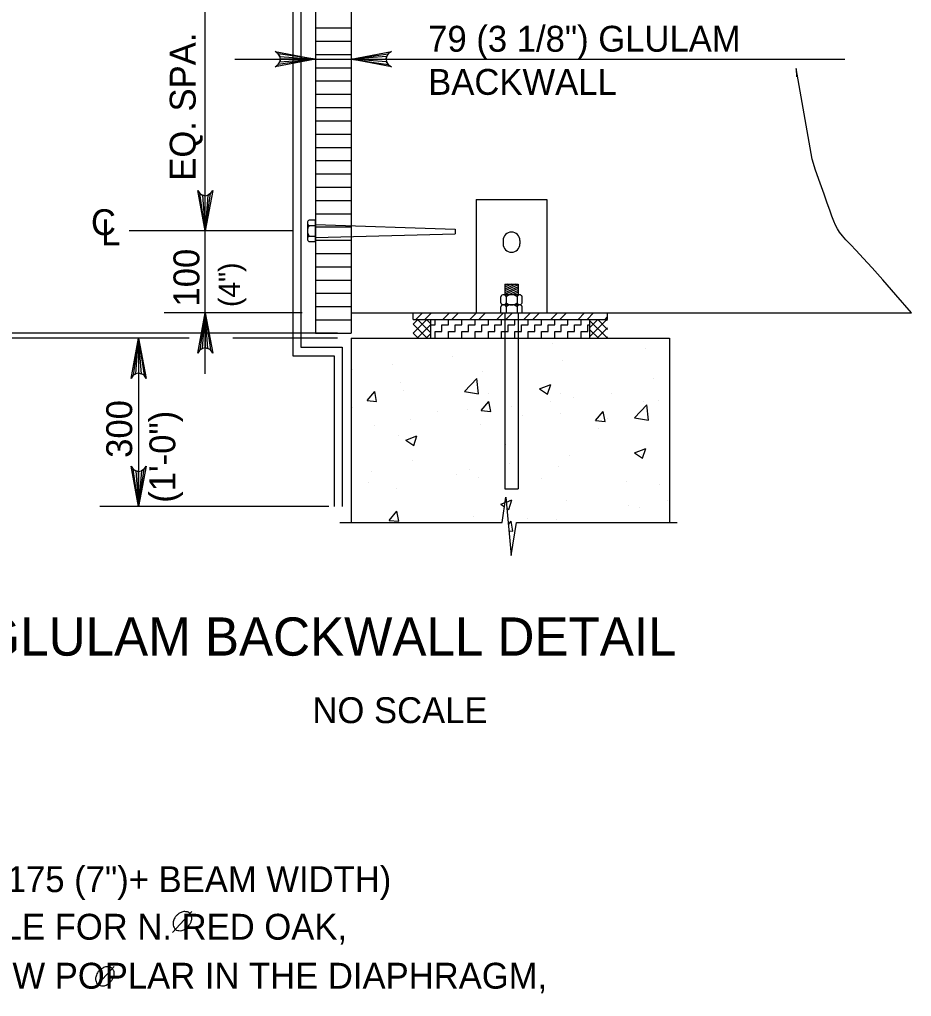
# Model space of a CAD drawing. Extents: x -13 to 81, y -176 to 0.
# Drawn here: x 47.852 to 51.986, y -10.168 to -5.639 of the extents above; entities that cross this region are included whole.
import ezdxf

# ---------------------------------------------------------------- set-up
doc = ezdxf.new("R2010")
doc.units = 0
for name, color, linetype in [('Level 3', 7, 'Continuous'), ('Level 4', 7, 'Continuous'), ('Level 5', 7, 'Continuous'), ('Level 7', 7, 'Continuous'), ('Level 8', 7, 'Continuous')]:
    doc.layers.add(name, color=color, linetype=linetype)

msp = doc.modelspace()

# ---------------------------------------------------------------- linework, layer by layer
at = {"layer": 'Level 3'}
for p, q in [((48.7129, -6.6186), (48.7129, -5.3997)), ((48.8506, -5.8229), (51.677, -5.8229)), ((49.1216, -6.6186), (48.3609, -6.6186)), ((48.7129, -7.2812), (48.7129, -6.6186)), ((49.1623, -6.9992), (48.5222, -6.9992)), ((48.6545, -7.0929), (47.2888, -7.0929)), ((49.1622, -7.0929), (48.8196, -7.0929)), ((48.3767, -7.1164), (48.2243, -7.1164)), ((48.4043, -7.1164), (48.4043, -7.8965)), ((49.2853, -7.8965), (48.2243, -7.8965))]:
    msp.add_line(p, q, dxfattribs=at)
for points in [[(49.2237, -5.8229), (49.0373, -5.8578), (49.0517, -5.8479), (49.0591, -5.8354), (49.0613, -5.8229), (49.0591, -5.8104), (49.0517, -5.7979), (49.0373, -5.7879), (49.2237, -5.8229), (49.0517, -5.7979), (49.0591, -5.8104), (49.2237, -5.8229), (49.0613, -5.8229), (49.0591, -5.8354), (49.2237, -5.8229), (49.0517, -5.8479)], [(49.3892, -5.8229), (49.5756, -5.7879), (49.5613, -5.7979), (49.5538, -5.8104), (49.5517, -5.8229), (49.5538, -5.8354), (49.5613, -5.8479), (49.5756, -5.8578), (49.3892, -5.8229), (49.5613, -5.8479), (49.5538, -5.8354), (49.3892, -5.8229), (49.5517, -5.8229), (49.5538, -5.8104), (49.3892, -5.8229), (49.5613, -5.7979)], [(48.7129, -6.6186), (48.678, -6.4322), (48.6879, -6.4465), (48.7004, -6.4539), (48.7129, -6.4561), (48.7254, -6.4539), (48.7379, -6.4465), (48.7478, -6.4322), (48.7129, -6.6186), (48.7379, -6.4465), (48.7254, -6.4539), (48.7129, -6.6186), (48.7129, -6.4561), (48.7004, -6.4539), (48.7129, -6.6186), (48.6879, -6.4465)], [(48.7129, -6.9992), (48.7478, -7.1856), (48.7379, -7.1712), (48.7254, -7.1638), (48.7129, -7.1617), (48.7004, -7.1638), (48.6879, -7.1712), (48.678, -7.1856), (48.7129, -6.9992), (48.6879, -7.1712), (48.7004, -7.1638), (48.7129, -6.9992), (48.7129, -7.1617), (48.7254, -7.1638), (48.7129, -6.9992), (48.7379, -7.1712)], [(48.4043, -7.1164), (48.4393, -7.3028), (48.4293, -7.2885), (48.4168, -7.2811), (48.4043, -7.2789), (48.3918, -7.2811), (48.3793, -7.2885), (48.3694, -7.3028), (48.4043, -7.1164), (48.3793, -7.2885), (48.3918, -7.2811), (48.4043, -7.1164), (48.4043, -7.2789), (48.4168, -7.2811), (48.4043, -7.1164), (48.4293, -7.2885)], [(48.4043, -7.8965), (48.3694, -7.7101), (48.3793, -7.7244), (48.3918, -7.7318), (48.4043, -7.734), (48.4168, -7.7318), (48.4293, -7.7244), (48.4393, -7.7101), (48.4043, -7.8965), (48.4293, -7.7244), (48.4168, -7.7318), (48.4043, -7.8965), (48.4043, -7.734), (48.3918, -7.7318), (48.4043, -7.8965), (48.3793, -7.7244)]]:
    msp.add_lwpolyline(points, dxfattribs=at)
at = {"layer": 'Level 4'}
for p, q in [((48.5608, -9.8718), (48.6504, -9.7737)), ((48.2018, -10.1275), (48.2914, -10.0294))]:
    msp.add_line(p, q, dxfattribs=at)
for points in [[(48.6412, -9.7833), (48.6341, -9.7779), (48.6271, -9.776), (48.6184, -9.7752), (48.6133, -9.7752), (48.6047, -9.7772), (48.5968, -9.7808), (48.5913, -9.7839), (48.5808, -9.7924), (48.5724, -9.8032), (48.5674, -9.8133), (48.5645, -9.8225), (48.5636, -9.8312), (48.5645, -9.8385), (48.5682, -9.8491), (48.572, -9.8545), (48.5796, -9.8604), (48.5912, -9.8632), (48.6044, -9.8628), (48.6212, -9.8551), (48.6333, -9.8447), (48.6425, -9.8319), (48.6485, -9.8187), (48.6505, -9.804), (48.6479, -9.7945), (48.6416, -9.7833)], [(48.2822, -10.0391), (48.2751, -10.0337), (48.2681, -10.0317), (48.2594, -10.031), (48.2542, -10.031), (48.2458, -10.0329), (48.2377, -10.0366), (48.2323, -10.0397), (48.2218, -10.0482), (48.2134, -10.0589), (48.2084, -10.069), (48.2055, -10.0782), (48.2046, -10.0869), (48.2055, -10.0942), (48.2092, -10.1048), (48.213, -10.1102), (48.2206, -10.1162), (48.2322, -10.1189), (48.2454, -10.1185), (48.2622, -10.1108), (48.2743, -10.1004), (48.2835, -10.0877), (48.2895, -10.0744), (48.2915, -10.0597), (48.2889, -10.0503), (48.2826, -10.0391)]]:
    msp.add_spline(points, degree=3, dxfattribs=at)
at = {"layer": 'Level 5'}
for p, q in [((49.2237, -3.1736), (49.2237, -7.0929)), ((49.119, -3.2621), (49.119, -7.198)), ((49.156, -3.3007), (49.156, -7.1582)), ((49.3892, -3.8148), (49.3892, -7.0929)), ((49.9695, -6.4742), (50.2958, -6.4742)), ((49.9695, -6.4742), (49.9695, -6.9992)), ((50.2958, -6.4742), (50.2958, -6.9992)), ((49.1863, -6.5811), (49.1863, -6.657)), ((49.2237, -6.5888), (49.8712, -6.6107)), ((49.8712, -6.6107), (49.8712, -6.6327)), ((49.2237, -6.6502), (49.8712, -6.6327)), ((50.0936, -6.6633), (50.0936, -6.679)), ((50.1717, -6.6633), (50.1717, -6.679)), ((50.1019, -6.8662), (50.1019, -6.9155)), ((50.1019, -6.8662), (50.1634, -6.8662)), ((50.1326, -6.8662), (50.1019, -6.8803)), ((50.1512, -6.8662), (50.1019, -6.8888)), ((50.1139, -6.8662), (50.1019, -6.8717)), ((50.1634, -6.8692), (50.1019, -6.8974)), ((50.1634, -6.8777), (50.1019, -6.9059)), ((50.1634, -6.8662), (50.1634, -6.9155)), ((50.0827, -6.9529), (50.0827, -6.9243)), ((50.171, -6.9155), (50.0952, -6.9155)), ((50.1634, -6.8862), (50.1019, -6.9145)), ((50.1086, -6.9243), (50.1086, -6.9529)), ((50.1634, -6.8948), (50.1182, -6.9156)), ((50.1634, -6.9034), (50.137, -6.9155)), ((50.1634, -6.9119), (50.1557, -6.9155)), ((50.1585, -6.9243), (50.1585, -6.9529)), ((50.1827, -6.9529), (50.1827, -6.9243)), ((50.0827, -6.9992), (50.0827, -6.9706)), ((50.171, -6.9617), (50.0952, -6.9617)), ((50.1086, -6.9706), (50.1086, -6.9992)), ((50.1585, -6.9706), (50.1585, -6.9992)), ((50.1827, -6.9992), (50.1827, -6.9706)), ((49.3892, -6.9992), (51.9864, -6.9992)), ((49.6763, -6.9992), (50.5782, -6.9992)), ((49.6763, -7.03), (49.6763, -6.9992)), ((49.6892, -7.03), (49.7199, -6.9992)), ((49.7309, -7.03), (49.7617, -6.9992)), ((49.8144, -7.03), (49.8453, -6.9992)), ((49.8562, -7.03), (49.887, -6.9992)), ((49.9397, -7.03), (49.9705, -6.9992)), ((49.9814, -7.03), (50.0123, -6.9992)), ((50.065, -7.03), (50.0957, -6.9992)), ((50.0827, -6.9992), (50.1827, -6.9992)), ((50.1019, -6.9992), (50.1019, -7.8142)), ((50.1067, -7.03), (50.1375, -6.9992)), ((50.1634, -6.9992), (50.1634, -7.8142)), ((50.1902, -7.03), (50.2211, -6.9992)), ((50.232, -7.03), (50.2628, -6.9992)), ((50.3155, -7.03), (50.3463, -6.9992)), ((50.3573, -7.03), (50.3881, -6.9992)), ((50.4408, -7.03), (50.4716, -6.9992)), ((50.4826, -7.03), (50.5133, -6.9992)), ((50.5661, -7.03), (50.5782, -7.0177)), ((50.5782, -7.03), (50.5782, -6.9992)), ((49.6763, -7.03), (50.5782, -7.03)), ((49.6763, -7.0934), (49.7398, -7.03)), ((49.6763, -7.0517), (49.698, -7.03)), ((49.7417, -7.1164), (49.6763, -7.0511)), ((49.6951, -7.1164), (49.7582, -7.0532)), ((49.7582, -7.0912), (49.697, -7.03)), ((49.7582, -7.0495), (49.7387, -7.03)), ((49.7582, -7.1164), (49.7582, -7.03)), ((49.7582, -7.0552), (49.7792, -7.0552)), ((49.7792, -7.0552), (49.7792, -7.03)), ((49.8099, -7.0552), (49.8407, -7.0552)), ((49.8099, -7.0859), (49.8099, -7.0552)), ((49.8407, -7.0552), (49.8407, -7.03)), ((49.8714, -7.0552), (49.9022, -7.0552)), ((49.8714, -7.0859), (49.8714, -7.0552)), ((49.9022, -7.0552), (49.9022, -7.03)), ((49.9329, -7.0552), (49.9637, -7.0552)), ((49.9329, -7.0859), (49.9329, -7.0552)), ((49.9637, -7.0552), (49.9637, -7.03)), ((49.9944, -7.0552), (50.0252, -7.0552)), ((49.9944, -7.0859), (49.9944, -7.0552)), ((50.0252, -7.0552), (50.0252, -7.03)), ((50.0559, -7.0552), (50.0867, -7.0552)), ((50.0559, -7.0859), (50.0559, -7.0552)), ((50.0867, -7.0552), (50.0867, -7.03)), ((50.1175, -7.0552), (50.1482, -7.0552)), ((50.1175, -7.0859), (50.1175, -7.0552)), ((50.1482, -7.0552), (50.1482, -7.03)), ((50.179, -7.0552), (50.2097, -7.0552)), ((50.179, -7.0859), (50.179, -7.0552)), ((50.2097, -7.0552), (50.2097, -7.03)), ((50.2405, -7.0552), (50.2712, -7.0552)), ((50.2405, -7.0859), (50.2405, -7.0552)), ((50.2712, -7.0552), (50.2712, -7.03)), ((50.302, -7.0552), (50.3327, -7.0552)), ((50.302, -7.0859), (50.302, -7.0552)), ((50.3327, -7.0552), (50.3327, -7.03)), ((50.3635, -7.0552), (50.3942, -7.0552)), ((50.3635, -7.0859), (50.3635, -7.0552)), ((50.3942, -7.0552), (50.3942, -7.03)), ((50.425, -7.0552), (50.4558, -7.0552)), ((50.425, -7.0859), (50.425, -7.0552)), ((50.4558, -7.0552), (50.4558, -7.03)), ((50.4866, -7.0552), (50.4963, -7.0552)), ((50.4866, -7.0859), (50.4866, -7.0552)), ((50.4964, -7.0667), (50.5332, -7.03)), ((50.4964, -7.1085), (50.5749, -7.03)), ((50.4964, -7.1164), (50.4964, -7.03)), ((50.5768, -7.1164), (50.4964, -7.036)), ((50.5782, -7.0761), (50.5322, -7.03)), ((50.5782, -7.0343), (50.5739, -7.03)), ((49.6999, -7.1164), (49.6763, -7.0928)), ((49.7368, -7.1164), (49.7582, -7.0951)), ((49.7792, -7.0859), (49.8099, -7.0859)), ((49.7792, -7.1164), (49.7792, -7.0859)), ((49.8407, -7.0859), (49.8714, -7.0859)), ((49.8407, -7.1164), (49.8407, -7.0859)), ((49.9022, -7.0859), (49.9329, -7.0859)), ((49.9022, -7.1164), (49.9022, -7.0859)), ((49.9637, -7.0859), (49.9944, -7.0859)), ((49.9637, -7.1164), (49.9637, -7.0859)), ((50.0252, -7.0859), (50.0559, -7.0859)), ((50.0252, -7.1164), (50.0252, -7.0859)), ((50.0867, -7.0859), (50.1175, -7.0859)), ((50.0867, -7.1164), (50.0867, -7.0859)), ((50.1482, -7.0859), (50.179, -7.0859)), ((50.1482, -7.1164), (50.1482, -7.0859)), ((50.2097, -7.0859), (50.2405, -7.0859)), ((50.2097, -7.1164), (50.2097, -7.0859)), ((50.2712, -7.0859), (50.302, -7.0859)), ((50.2712, -7.1164), (50.2712, -7.0859)), ((50.3327, -7.0859), (50.3635, -7.0859)), ((50.3327, -7.1164), (50.3327, -7.0859)), ((50.3942, -7.0859), (50.425, -7.0859)), ((50.3942, -7.1164), (50.3942, -7.0859)), ((50.4558, -7.0859), (50.4866, -7.0859)), ((50.4558, -7.1164), (50.4558, -7.0859)), ((50.5351, -7.1164), (50.4964, -7.0777)), ((50.5302, -7.1164), (50.5782, -7.0684)), ((50.572, -7.1164), (50.5782, -7.1102)), ((49.3892, -7.1164), (50.8656, -7.1164)), ((49.3892, -7.1164), (49.3892, -7.9703)), ((50.3249, -7.1409), (50.3249, -7.1409)), ((50.5097, -7.1166), (50.5097, -7.1166)), ((50.8656, -7.1164), (50.8656, -7.9703)), ((49.119, -7.198), (49.3108, -7.198)), ((49.156, -7.1582), (49.3478, -7.1582)), ((49.3108, -7.198), (49.3108, -7.8965)), ((49.3478, -7.1582), (49.3478, -7.8965)), ((50.7522, -7.1664), (50.7522, -7.1664)), ((49.5791, -7.2391), (49.5791, -7.2391)), ((49.8587, -7.2022), (49.8587, -7.2022)), ((50.3688, -7.2218), (50.3688, -7.2218)), ((49.3943, -7.2634), (49.3943, -7.2634)), ((49.9959, -7.269), (49.9959, -7.269)), ((49.6169, -7.321), (49.6169, -7.321)), ((49.9145, -7.3636), (49.972, -7.3037)), ((49.9802, -7.3738), (49.972, -7.3037)), ((50.2627, -7.351), (50.3145, -7.3312)), ((50.2995, -7.3758), (50.3145, -7.3312)), ((50.7902, -7.3012), (50.7902, -7.3012)), ((49.4632, -7.4059), (49.4988, -7.3636)), ((49.5073, -7.4098), (49.4988, -7.3636)), ((49.6317, -7.3572), (49.6317, -7.3572)), ((49.9145, -7.3636), (49.9802, -7.3738)), ((50.0257, -7.3739), (50.0257, -7.3739)), ((50.2627, -7.351), (50.2995, -7.3758)), ((50.3597, -7.3751), (50.3597, -7.3751)), ((50.5951, -7.3709), (50.5951, -7.3709)), ((49.4632, -7.4059), (49.5073, -7.4098)), ((49.9927, -7.4522), (50.0282, -7.4098)), ((50.0368, -7.4562), (50.0282, -7.4099)), ((50.3155, -7.4078), (50.3155, -7.4078)), ((50.4198, -7.3905), (50.4198, -7.3905)), ((50.7023, -7.4858), (50.7598, -7.4259)), ((50.7432, -7.4122), (50.7432, -7.4122)), ((50.7679, -7.496), (50.7598, -7.4259)), ((50.8138, -7.4072), (50.8138, -7.4072)), ((49.3933, -7.4398), (49.3933, -7.4398)), ((49.7873, -7.4564), (49.7873, -7.4564)), ((49.9292, -7.449), (49.9292, -7.449)), ((49.9927, -7.4522), (50.0368, -7.4562)), ((50.1307, -7.4321), (50.1307, -7.4321)), ((50.3598, -7.4675), (50.3598, -7.4675)), ((50.5222, -7.4986), (50.5577, -7.4562)), ((50.5662, -7.5025), (50.5577, -7.4562)), ((49.6645, -7.4934), (49.6645, -7.4934)), ((49.987, -7.5147), (49.987, -7.5147)), ((50.1813, -7.4731), (50.1813, -7.4731)), ((50.5222, -7.4986), (50.5662, -7.5024)), ((50.5754, -7.4897), (50.5754, -7.4897)), ((50.7023, -7.4858), (50.7679, -7.496)), ((49.4987, -7.5229), (49.4987, -7.5229)), ((50.5366, -7.5372), (50.5366, -7.5372)), ((49.608, -7.5667), (49.608, -7.5667)), ((49.6426, -7.5891), (49.6942, -7.5692)), ((49.6426, -7.5891), (49.6792, -7.6138)), ((49.6792, -7.6138), (49.6942, -7.5692)), ((50.1061, -7.6111), (50.1061, -7.6111)), ((50.7034, -7.6482), (50.7551, -7.6283)), ((50.7034, -7.6482), (50.7402, -7.673)), ((50.7402, -7.673), (50.7551, -7.6284)), ((49.6756, -7.685), (49.6756, -7.685)), ((50.1213, -7.6989), (50.1213, -7.6989)), ((50.4009, -7.6621), (50.4009, -7.6621)), ((50.7342, -7.6578), (50.7342, -7.6578)), ((49.4847, -7.7325), (49.4847, -7.7325)), ((49.9365, -7.7232), (49.9365, -7.7232)), ((50.3508, -7.7132), (50.3508, -7.7132)), ((49.4703, -7.7846), (49.4703, -7.7846)), ((49.8788, -7.7491), (49.8788, -7.7491)), ((49.978, -7.7605), (49.978, -7.7605)), ((50.2729, -7.7657), (50.2729, -7.7657)), ((50.667, -7.7824), (50.667, -7.7824)), ((49.599, -7.8125), (49.599, -7.8125)), ((50.1019, -7.8142), (50.1634, -7.8142)), ((50.8185, -7.7955), (50.8185, -7.7955)), ((50.0832, -7.8863), (50.1032, -7.8787)), ((50.0887, -7.9703), (50.107, -7.8543)), ((50.107, -7.8543), (50.1307, -8.1246)), ((50.1089, -7.8764), (50.1348, -7.8664)), ((50.1199, -7.9111), (50.1348, -7.8665)), ((50.388, -7.8694), (50.388, -7.8694)), ((50.8577, -7.8675), (50.8577, -7.8675)), ((49.5657, -7.9612), (49.6013, -7.9188)), ((49.6097, -7.9651), (49.6013, -7.9188)), ((50.0832, -7.8863), (50.1002, -7.8977)), ((50.1115, -7.9054), (50.1199, -7.9111)), ((50.6729, -7.8918), (50.6729, -7.8918)), ((50.7252, -7.9036), (50.7252, -7.9036)), ((49.3364, -7.9703), (50.0887, -7.9703)), ((49.5657, -7.9612), (49.6097, -7.9651)), ((49.9575, -7.9433), (49.9575, -7.9433)), ((50.118, -7.9802), (50.1307, -7.9651)), ((50.1392, -8.0114), (50.1307, -7.9652)), ((50.1307, -8.1246), (50.1552, -7.9703)), ((50.1552, -7.9703), (50.9012, -7.9703)), ((50.2067, -7.9532), (50.2067, -7.9532)), ((50.3418, -7.959), (50.3418, -7.959)), ((50.1206, -8.0098), (50.1392, -8.0114))]:
    msp.add_line(p, q, dxfattribs=at)
msp.add_lwpolyline([(50.1907, -3.8148), (50.1743, -3.8148), (49.3892, -3.8148), (49.3892, -6.3787)], dxfattribs=at)
for centre, radius, start, end in [((49.1989, -6.5816), 0.0126, 107.4518, 252.5482), ((49.226, -6.6186), 0.0397, 141.05, 218.95), ((49.2002, -6.6565), 0.0139, 111.2869, 178.1729), ((49.2002, -6.6565), 0.0139, 178.1729, 248.7131), ((50.1326, -6.6633), 0.039, 0, 180), ((50.1326, -6.679), 0.039, 180, 0), ((50.0956, -6.9294), 0.0139, 88.1729, 158.7131), ((50.0956, -6.9294), 0.0139, 21.2869, 88.1729), ((50.1335, -6.9552), 0.0398, 51.05, 128.95), ((50.1705, -6.9281), 0.0126, 17.4518, 162.5482), ((50.0956, -6.9479), 0.0139, 201.2869, 271.8271), ((50.0956, -6.9756), 0.0139, 88.1729, 158.7131), ((50.0956, -6.9479), 0.0139, 271.8271, 338.7131), ((50.0956, -6.9756), 0.0139, 21.2869, 88.1729), ((50.1335, -6.922), 0.0398, 231.05, 308.95), ((50.1335, -7.0015), 0.0398, 51.05, 128.95), ((50.1705, -6.9491), 0.0126, 197.4518, 342.5482), ((50.1705, -6.9744), 0.0126, 17.4518, 162.5482)]:
    msp.add_arc(centre, radius, start, end, dxfattribs=at)
at = {"layer": 'Level 7'}
for p, q in [((49.2237, -5.6781), (49.3892, -5.6781)), ((49.2237, -5.7396), (49.3892, -5.7396)), ((49.2237, -5.8011), (49.3892, -5.8011)), ((49.2237, -5.8626), (49.3892, -5.8626)), ((49.2237, -5.9241), (49.3892, -5.9241)), ((49.2237, -5.9857), (49.3892, -5.9857)), ((49.2237, -6.0472), (49.3892, -6.0472)), ((49.2237, -6.1087), (49.3892, -6.1087)), ((49.2237, -6.1702), (49.3892, -6.1702)), ((49.2237, -6.2317), (49.3892, -6.2317)), ((49.2237, -6.2932), (49.3892, -6.2932)), ((49.2237, -6.3548), (49.3892, -6.3548)), ((49.2237, -6.4162), (49.3892, -6.4162)), ((49.2237, -6.4777), (49.3892, -6.4777)), ((49.2237, -6.5393), (49.3892, -6.5393)), ((49.2237, -6.5695), (49.1952, -6.5695)), ((49.1952, -6.5936), (49.2237, -6.5936)), ((49.2237, -6.6695), (49.2237, -6.5695)), ((49.2237, -6.6007), (49.3892, -6.6007)), ((49.1952, -6.6436), (49.2237, -6.6436)), ((49.2237, -6.6695), (49.1952, -6.6695)), ((49.2237, -6.6623), (49.3892, -6.6623)), ((49.2237, -6.7238), (49.3892, -6.7238)), ((49.2237, -6.7853), (49.3892, -6.7853)), ((49.2237, -6.8468), (49.3892, -6.8468)), ((49.2237, -6.9083), (49.3892, -6.9083)), ((49.2237, -6.9699), (49.3892, -6.9699)), ((49.2237, -7.0314), (49.3892, -7.0314)), ((49.2237, -7.0929), (49.3892, -7.0929))]:
    msp.add_line(p, q, dxfattribs=at)
for points in [[(51.5264, -6.2866), (51.4523, -5.8669), (51.4539, -5.9056)], [(51.9864, -6.9992), (51.9147, -6.9155), (51.8543, -6.8466), (51.8041, -6.7908), (51.7629, -6.7461), (51.7297, -6.7107), (51.7033, -6.6828), (51.6826, -6.6605), (51.6663, -6.642), (51.6535, -6.6254), (51.6431, -6.6094), (51.6342, -6.5926), (51.6259, -6.5736), (51.6174, -6.551), (51.6077, -6.5236), (51.5961, -6.4898), (51.5813, -6.4485), (51.5631, -6.3983), (51.5424, -6.3383), (51.5264, -6.2866)]]:
    msp.add_lwpolyline(points, dxfattribs=at)
at = {"layer": 'Level 8'}
for p, q in [((49.3267, -7.0929), (47.2861, -7.0929)), ((48.6385, -7.1164), (47.286, -7.1164)), ((49.3266, -7.1164), (48.8409, -7.1164))]:
    msp.add_line(p, q, dxfattribs=at)

# ---------------------------------------------------------------- texts
at = {"layer": 'Level 3'}
for s, height, p in [('79 (3 1/8") GLULAM', 0.12, (49.7465, -5.7883)), ('BACKWALL', 0.12, (49.7465, -5.9883)), ('C', 0.12, (48.1832, -6.6388)), ('L', 0.12, (48.2302, -6.6858)), ('GLULAM BACKWALL DETAIL', 0.177167, (47.6715, -8.5883)), ('NO SCALE', 0.12, (49.2099, -8.9012)), ('L 19.1 (3/4")  LAG SCREW (LENGTH OF LAG SCREW = 175 (7")+ BEAM WIDTH)', 0.12, (43.6566, -9.6847)), ('W/ 50.8 (2")O.D. STD. WASHER & 15.9 (5/8")  PILOT HOLE FOR N. RED OAK, ', 0.12, (43.6566, -9.9052)), ('14.3 (9/16")  FOR RED MAPLE & 12.7 (1/2")  FOR YELLOW POPLAR IN THE DIAPHRAGM, ', 0.12, (43.6566, -10.1322))]:
    msp.add_text(s, height=height, dxfattribs=at).set_placement(p)
for s, height, p in [('EQ. SPA.', 0.12, (48.6686, -6.3865)), ('100', 0.12, (48.6857, -6.9697)), ('(4")', 0.09774, (48.8737, -6.9719)), ('300', 0.12, (48.3743, -7.6712)), ('(1\'-0")', 0.12, (48.5743, -7.8795))]:
    msp.add_text(s, height=height, rotation=90, dxfattribs=at).set_placement(p)

doc.saveas('drawing.dxf')
